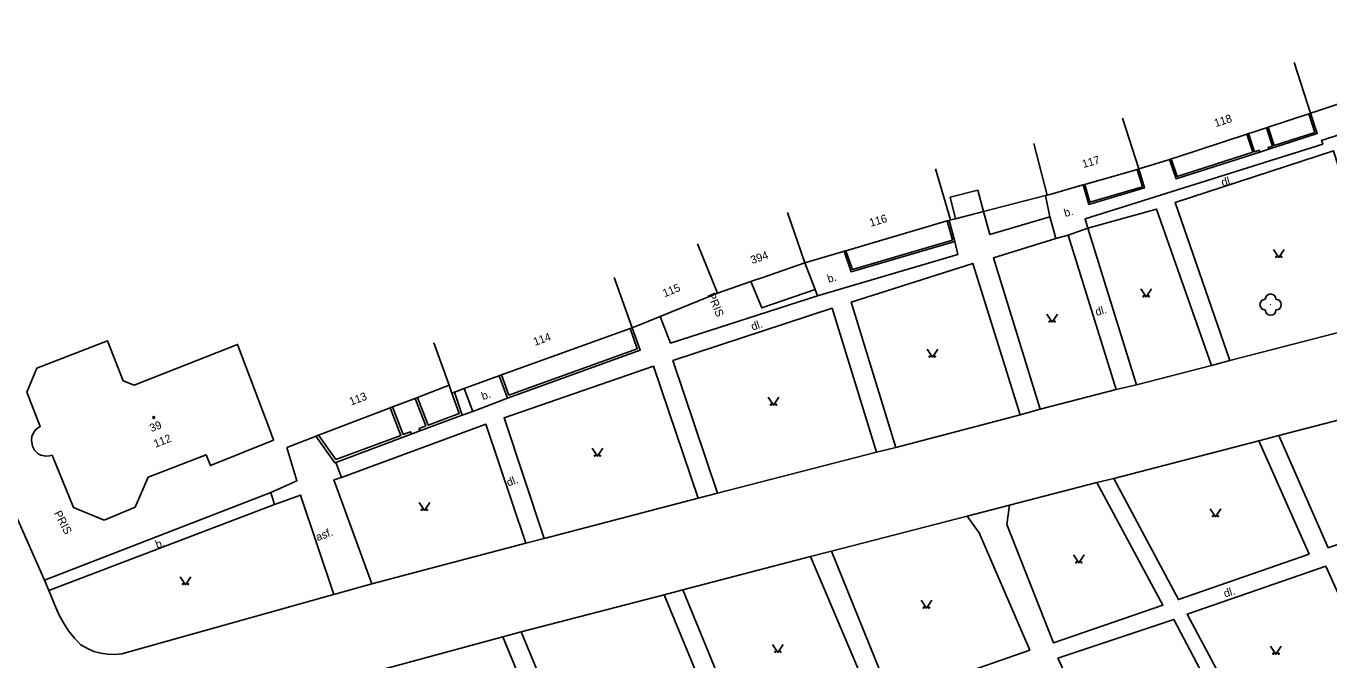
# Model space of a CAD drawing. Extents: x -577457 to -568404, y -1208466 to -1201387.
# Drawn here: x -575095.5 to -574973.4, y -1204045.2 to -1203985.8 of the extents above; entities that cross this region are included whole.
import ezdxf

# ---------------------------------------------------------------- set-up
doc = ezdxf.new("R2010")
doc.units = 0
for name, color, linetype in [('BUDOVY_MĚŘ', 7, 'Continuous'), ('BUDOVY_NEMĚŘ', 7, 'Continuous'), ('POMOC_POPIS', 7, 'Continuous'), ('ROZHRANÍ_PLOCH', 7, 'Continuous'), ('ZELEŇ', 7, 'Continuous'), ('ZN_BUDOV', 7, 'Continuous'), ('ZN_DOPLŇKOVÉ', 7, 'Continuous'), ('ZN_KULTUR', 7, 'Continuous'), ('Č_POPIS_ORIENT', 7, 'Continuous')]:
    doc.layers.add(name, color=color, linetype=linetype)

msp = doc.modelspace()

# ---------------------------------------------------------------- linework, layer by layer
at = {"layer": 'BUDOVY_MĚŘ'}
for points in [[(-574976.64, -1203989.22), (-574975.1, -1203993.98)], [(-574975.26, -1203994.03), (-574979.06, -1203995.28)], [(-574975.1, -1203993.98), (-574975.26, -1203994.03)], [(-574975.1, -1203993.98), (-574974.59, -1203993.81)], [(-574992.74, -1203994.44), (-574991.2, -1203999.2)], [(-574979.22, -1203995.33), (-574979.45, -1203995.41)], [(-574979.06, -1203995.28), (-574979.22, -1203995.33)], [(-574981.07, -1203995.94), (-574987.62, -1203998.09), (-574988.16, -1203998.26)], [(-574980.91, -1203995.89), (-574981.07, -1203995.94)], [(-574980.49, -1203995.75), (-574980.91, -1203995.89)], [(-575001.04, -1203996.81), (-574999.8, -1204001.66)], [(-574988.32, -1203998.31), (-574989.02, -1203998.53)], [(-574988.16, -1203998.26), (-574988.32, -1203998.31)], [(-575010.25, -1203999.18), (-575008.84, -1204003.98)], [(-574991.35, -1203999.24), (-574996.25, -1204000.64)], [(-574991.2, -1203999.2), (-574991.35, -1203999.24)], [(-574990.99, -1203999.13), (-574991.2, -1203999.2)], [(-574996.41, -1204000.69), (-574996.75, -1204000.79)], [(-574996.25, -1204000.64), (-574996.41, -1204000.69)], [(-575005.77, -1204003.19), (-574999.94, -1204001.7)], [(-574999.94, -1204001.7), (-574999.8, -1204001.66)], [(-574999.41, -1204001.55), (-574999.8, -1204001.66)], [(-575024.13, -1204003.27), (-575022.49, -1204007.99)], [(-575008.84, -1204003.98), (-575008.37, -1204003.86)], [(-575008.37, -1204003.86), (-575005.77, -1204003.19)], [(-575018.65, -1204006.86), (-575009.15, -1204004.07)], [(-575009.15, -1204004.07), (-575008.98, -1204004.02)], [(-575008.98, -1204004.02), (-575008.84, -1204003.98)], [(-575032.58, -1204006.2), (-575030.7, -1204010.83)], [(-575019.11, -1204007), (-575018.82, -1204006.91)], [(-575018.82, -1204006.91), (-575018.65, -1204006.86)], [(-575026.53, -1204009.39), (-575022.49, -1204007.99)], [(-575022.49, -1204007.99), (-575021.65, -1204007.74)], [(-575040.38, -1204009.38), (-575038.68, -1204014.08)], [(-575030.7, -1204010.83), (-575027.57, -1204009.75)], [(-575027.57, -1204009.75), (-575027.4, -1204009.69)], [(-575036.06, -1204013.01), (-575030.7, -1204010.83)], [(-575050.94, -1204018.5), (-575038.89, -1204014.16)], [(-575038.89, -1204014.16), (-575038.68, -1204014.08)], [(-575038.68, -1204014.08), (-575038.37, -1204013.95)], [(-575057.29, -1204015.48), (-575055.85, -1204019.47)], [(-575051.43, -1204018.68), (-575051.15, -1204018.58)], [(-575051.15, -1204018.58), (-575050.94, -1204018.5)], [(-575055.85, -1204019.47), (-575058.81, -1204020.6)], [(-575055.85, -1204019.47), (-575055.59, -1204020.19)], [(-575055.35, -1204020.1), (-575054.45, -1204019.77)], [(-575054.45, -1204019.77), (-575054.28, -1204019.71)], [(-575059.04, -1204020.69), (-575059.46, -1204020.85)], [(-575058.81, -1204020.6), (-575059.04, -1204020.69)], [(-575055.59, -1204020.19), (-575055.35, -1204020.1)], [(-575061.37, -1204021.58), (-575068.09, -1204024.15)], [(-575061.14, -1204021.49), (-575061.37, -1204021.58)], [(-575060.72, -1204021.33), (-575061.14, -1204021.49)], [(-575068.33, -1204024.24), (-575068.47, -1204024.29)], [(-575068.09, -1204024.15), (-575068.33, -1204024.24)]]:
    msp.add_lwpolyline(points, dxfattribs=at)
at = {"layer": 'BUDOVY_NEMĚŘ'}
msp.add_lwpolyline([(-575088.18, -1204032.09), (-575091.07, -1204030.91), (-575093.07, -1204026.03), (-575093.32, -1204026.08), (-575093.65, -1204026.12), (-575094.11, -1204026.02), (-575094.38, -1204025.88), (-575094.72, -1204025.55), (-575094.89, -1204025.18), (-575095, -1204024.63), (-575094.97, -1204024.23), (-575094.72, -1204023.76), (-575094.52, -1204023.55), (-575094.17, -1204023.34), (-575095.44, -1204020.11), (-575094.49, -1204017.85), (-575087.87, -1204015.3), (-575086.39, -1204019.05), (-575085.36, -1204019.46), (-575075.68, -1204015.64), (-575072.57, -1204023.89), (-575072.31, -1204024.6), (-575078.22, -1204026.99), (-575078.63, -1204025.97), (-575084.06, -1204028.08), (-575085.29, -1204030.9), (-575088.18, -1204032.09)], dxfattribs=at)
at = {"layer": 'ROZHRANÍ_PLOCH'}
for points in [[(-574995.99, -1204004.75), (-574996.24, -1204003.87), (-574973.96, -1203996.86), (-574974.07, -1203996.52), (-574957.69, -1203991.15), (-574957.42, -1203991.67), (-574939.91, -1203985.81), (-574939.38, -1203987.25)], [(-574982.66, -1204017.14), (-574987.79, -1204002.33), (-574972.94, -1203997.49), (-574968, -1204013.37)], [(-574979.86, -1203997.62), (-574979.01, -1203997.34)], [(-575093.77, -1204037.74), (-575110.49, -1204000)], [(-574999.53, -1204003.67), (-574999.94, -1204001.7)], [(-575005.77, -1204003.19), (-575005.17, -1204005.33), (-574999.53, -1204003.67)], [(-574999.53, -1204003.67), (-574999.24, -1204004.77), (-574998.98, -1204005.71)], [(-574995.99, -1204004.75), (-574989.54, -1204002.96), (-574984.37, -1204017.6)], [(-574997.81, -1204005.41), (-574995.99, -1204004.75)], [(-574995.99, -1204004.75), (-574991.42, -1204019.41)], [(-575021.33, -1204011.08), (-575008.17, -1204007.2), (-575008.43, -1204005.99)], [(-575000.43, -1204021.72), (-575004.83, -1204007.53), (-574998.98, -1204005.71)], [(-574997.81, -1204005.41), (-574998.98, -1204005.71)], [(-574993.32, -1204019.86), (-574997.81, -1204005.41)], [(-575013.96, -1204025.29), (-575018.16, -1204011.69), (-575006.76, -1204008.05), (-575002.32, -1204022.24)], [(-575036.06, -1204013.01), (-575035.09, -1204015.51), (-575021.33, -1204011.08)], [(-575021.33, -1204011.08), (-575021.54, -1204010.5)], [(-575030.69, -1204029.59), (-575034.87, -1204017.15), (-575019.95, -1204012.25), (-575015.8, -1204025.74)], [(-574982.66, -1204017.14), (-574968, -1204013.37)], [(-574984.37, -1204017.6), (-574982.66, -1204017.14)], [(-575046.95, -1204033.82), (-575050.7, -1204022.51), (-575036.68, -1204017.68), (-575032.51, -1204030.05)], [(-574991.42, -1204019.41), (-574984.37, -1204017.6)], [(-575054.45, -1204019.77), (-575053.64, -1204021.91)], [(-574993.32, -1204019.86), (-574991.42, -1204019.41)], [(-575053.64, -1204021.91), (-575050.37, -1204020.66)], [(-575000.43, -1204021.72), (-574993.32, -1204019.86)], [(-575053.64, -1204021.91), (-575054.61, -1204022.27)], [(-575013.96, -1204025.29), (-575003.25, -1204022.5), (-575002.32, -1204022.24)], [(-575002.32, -1204022.24), (-575000.43, -1204021.72)], [(-574978.06, -1204024.16), (-574967.94, -1204021.55)], [(-574978.06, -1204024.16), (-574973.46, -1204034.69), (-574964.49, -1204031.47), (-574964.14, -1204030.9), (-574967.94, -1204021.55)], [(-575048.66, -1204034.25), (-575052.4, -1204023.11), (-575065.94, -1204028.11)], [(-574993.54, -1204028.2), (-574987.48, -1204039.54), (-574975.24, -1204035.29), (-574979.94, -1204024.67)], [(-574993.54, -1204028.2), (-574979.94, -1204024.67)], [(-574979.94, -1204024.67), (-574978.06, -1204024.16)], [(-575070.53, -1204028.6), (-575070.11, -1204028.41), (-575071.07, -1204025.29)], [(-575030.69, -1204029.59), (-575015.8, -1204025.74)], [(-575015.8, -1204025.74), (-575013.96, -1204025.29)], [(-575066.47, -1204026.7), (-575065.94, -1204028.11)], [(-575065.94, -1204028.11), (-575066.65, -1204028.34), (-575063.1, -1204038.08)], [(-574995.13, -1204028.58), (-574993.54, -1204028.2)], [(-575072.55, -1204029.5), (-575093.77, -1204037.74)], [(-575072.55, -1204029.5), (-575070.53, -1204028.6)], [(-575072.23, -1204030.63), (-575072.55, -1204029.5)], [(-575032.51, -1204030.05), (-575030.69, -1204029.59)], [(-575003.33, -1204030.7), (-575003.56, -1204032.5), (-574999.18, -1204043.61), (-574988.94, -1204040.06), (-574995.13, -1204028.58)], [(-575003.33, -1204030.7), (-574995.13, -1204028.58)], [(-575093.37, -1204038.7), (-575072.23, -1204030.63)], [(-575070.12, -1204029.88), (-575072.23, -1204030.63)], [(-575066.66, -1204039.06), (-575069.78, -1204029.76), (-575070.12, -1204029.88)], [(-575046.95, -1204033.82), (-575032.51, -1204030.05)], [(-575007.29, -1204031.73), (-575003.33, -1204030.7)], [(-575020.01, -1204035.01), (-575007.29, -1204031.73)], [(-575020.01, -1204035.01), (-575014.4, -1204048.81), (-575001.42, -1204044.29), (-575006.15, -1204033.29), (-575007.29, -1204031.73)], [(-575048.66, -1204034.25), (-575063.1, -1204038.08)], [(-575046.95, -1204033.82), (-575048.66, -1204034.25)], [(-575033.94, -1204038.63), (-575021.96, -1204035.5)], [(-575033.94, -1204038.63), (-575027.84, -1204053.48), (-575015.96, -1204049.67), (-575021.96, -1204035.5)], [(-575021.96, -1204035.5), (-575020.01, -1204035.01)], [(-574912.63, -1204177.88), (-574922.36, -1204159.6), (-574934.08, -1204138.15), (-574950.93, -1204107.14), (-574981.16, -1204051.23), (-574986.68, -1204040.91), (-574973.68, -1204036.43), (-574971.26, -1204041.76)], [(-575093.77, -1204037.74), (-575093.37, -1204038.7)], [(-575063.1, -1204038.08), (-575066.66, -1204039.06)], [(-575067.11, -1204039.18), (-575086.54, -1204044.63), (-575087.2, -1204044.69), (-575087.86, -1204044.67), (-575088.51, -1204044.57), (-575089.15, -1204044.4), (-575089.76, -1204044.14), (-575090.36, -1204043.8), (-575090.97, -1204043.16), (-575091.53, -1204042.46), (-575092.01, -1204041.71), (-575092.43, -1204040.93), (-575092.71, -1204040.29), (-575093.37, -1204038.7)], [(-575066.66, -1204039.06), (-575067.11, -1204039.18)], [(-575035.69, -1204039.1), (-575049.09, -1204042.57)], [(-575035.69, -1204039.1), (-575029.5, -1204054.06), (-575042.46, -1204058.57), (-575049.09, -1204042.57)], [(-575033.94, -1204038.63), (-575035.69, -1204039.1)], [(-574996.39, -1204050.09), (-574998.78, -1204045.04), (-574987.93, -1204041.41), (-574982.39, -1204051.92), (-574952.04, -1204107.85), (-574935.21, -1204138.91), (-574926.87, -1204154.13), (-574927.75, -1204154.64)], [(-575049.09, -1204042.57), (-575050.81, -1204043.04)], [(-575050.81, -1204043.04), (-575044.18, -1204059.11), (-575067.1, -1204067.02), (-575073.76, -1204049.24)], [(-575050.81, -1204043.04), (-575073.76, -1204049.24)]]:
    msp.add_lwpolyline(points, dxfattribs=at)
at = {"layer": 'ZELEŇ'}
msp.add_circle((-574978.84, -1204011.91), 0.0005, dxfattribs=at)
for centre, start, end in [((-574978.84, -1204011.41), 0, 180), ((-574979.34, -1204011.91), 90, 270), ((-574978.84, -1204012.41), 180, 360), ((-574978.34, -1204011.91), 270, 90)]:
    msp.add_arc(centre, 0.5, start, end, dxfattribs=at)
at = {"layer": 'ZN_BUDOV'}
msp.add_circle((-575083.54, -1204022.48), 0.0875, dxfattribs=at)
at = {"layer": 'ZN_DOPLŇKOVÉ'}
for points in [[(-574974.59, -1203993.81), (-574971.8, -1203992.89)], [(-574975.26, -1203994.03), (-574974.69, -1203995.78), (-574978.52, -1203997.01), (-574979.06, -1203995.28)], [(-574975.1, -1203993.98), (-574974.47, -1203995.89), (-574979.01, -1203997.34)], [(-574979.01, -1203997.34), (-574979.06, -1203997.18), (-574978.68, -1203997.06), (-574979.22, -1203995.33)], [(-574981.07, -1203995.94), (-574980.51, -1203997.64), (-574987.59, -1203999.9), (-574988.16, -1203998.26)], [(-574980.91, -1203995.89), (-574980.35, -1203997.59), (-574979.92, -1203997.45), (-574979.86, -1203997.62)], [(-574979.45, -1203995.41), (-574980.49, -1203995.75)], [(-574979.86, -1203997.62), (-574987.7, -1204000.11), (-574988.32, -1203998.31)], [(-574989.02, -1203998.53), (-574990.99, -1203999.13)], [(-574991.2, -1203999.2), (-574990.66, -1204000.97), (-574995.89, -1204002.52), (-574996.41, -1204000.69)], [(-574991.35, -1203999.24), (-574990.86, -1204000.87), (-574995.78, -1204002.32), (-574996.25, -1204000.64)], [(-575008.37, -1204003.86), (-575008.89, -1204001.85), (-575006.29, -1204001.19), (-575005.77, -1204003.19)], [(-574996.75, -1204000.79), (-574999.41, -1204001.55)], [(-575009.15, -1204004.07), (-575008.65, -1204005.87), (-575018.05, -1204008.61), (-575018.65, -1204006.86)], [(-575008.98, -1204004.02), (-575008.43, -1204005.99)], [(-575008.43, -1204005.99), (-575018.17, -1204008.83), (-575018.82, -1204006.91)], [(-575021.65, -1204007.74), (-575019.11, -1204007)], [(-575022.49, -1204007.99), (-575021.54, -1204010.5)], [(-575021.54, -1204010.5), (-575026.55, -1204012.2), (-575027.57, -1204009.75)], [(-575027.4, -1204009.69), (-575026.53, -1204009.39)], [(-575038.37, -1204013.95), (-575036.06, -1204013.01)], [(-575038.89, -1204014.16), (-575038.21, -1204016.04), (-575050.24, -1204020.38), (-575050.94, -1204018.5)], [(-575038.68, -1204014.08), (-575037.93, -1204016.18), (-575050.37, -1204020.66)], [(-575050.37, -1204020.66), (-575051.15, -1204018.58)], [(-575054.28, -1204019.71), (-575051.43, -1204018.68)], [(-575059.46, -1204020.85), (-575060.72, -1204021.33)], [(-575059.04, -1204020.69), (-575058.04, -1204023.28), (-575058.66, -1204023.51), (-575058.58, -1204023.74)], [(-575055.59, -1204020.19), (-575054.92, -1204022.12), (-575057.81, -1204023.19), (-575058.81, -1204020.6)], [(-575055.35, -1204020.1), (-575054.61, -1204022.27)], [(-575061.37, -1204021.58), (-575060.37, -1204024.16), (-575066.46, -1204026.43), (-575068.09, -1204024.15)], [(-575061.14, -1204021.49), (-575060.14, -1204024.07), (-575059.47, -1204023.82), (-575059.39, -1204024.06)], [(-575054.61, -1204022.27), (-575058.58, -1204023.74)], [(-575068.47, -1204024.29), (-575071.07, -1204025.29)], [(-575066.47, -1204026.7), (-575066.55, -1204026.73), (-575068.33, -1204024.24)], [(-575059.39, -1204024.06), (-575066.47, -1204026.7)], [(-575058.58, -1204023.74), (-575059.39, -1204024.06)]]:
    msp.add_lwpolyline(points, dxfattribs=at)
at = {"layer": 'ZN_KULTUR'}
for points in [[(-574978.58, -1204006.74), (-574978.08, -1204007.49), (-574977.58, -1204006.74)], [(-574991.01, -1204010.43), (-574990.51, -1204011.18), (-574990.01, -1204010.43)], [(-574999.83, -1204012.8), (-574999.33, -1204013.55), (-574998.83, -1204012.8)], [(-575011.05, -1204016.08), (-575010.55, -1204016.83), (-575010.05, -1204016.08)], [(-575025.93, -1204020.58), (-575025.43, -1204021.33), (-575024.93, -1204020.58)], [(-575042.45, -1204025.37), (-575041.95, -1204026.12), (-575041.45, -1204025.37)], [(-575058.67, -1204030.44), (-575058.17, -1204031.19), (-575057.67, -1204030.44)], [(-574984.52, -1204031.04), (-574984.02, -1204031.79), (-574983.52, -1204031.04)], [(-574997.32, -1204035.36), (-574996.82, -1204036.11), (-574996.32, -1204035.36)], [(-575081.05, -1204037.4), (-575080.55, -1204038.15), (-575080.05, -1204037.4)], [(-575011.61, -1204039.6), (-575011.11, -1204040.35), (-575010.61, -1204039.6)], [(-575025.53, -1204043.74), (-575025.03, -1204044.49), (-575024.53, -1204043.74)], [(-574978.84, -1204043.91), (-574978.34, -1204044.66), (-574977.84, -1204043.91)]]:
    msp.add_lwpolyline(points, dxfattribs=at)
for centre in [(-574978.33, -1204007.44), (-574977.83, -1204007.44), (-574990.76, -1204011.13), (-574990.26, -1204011.13), (-574999.58, -1204013.5), (-574999.08, -1204013.5), (-575010.8, -1204016.78), (-575010.3, -1204016.78), (-575025.68, -1204021.28), (-575025.18, -1204021.28), (-575042.2, -1204026.07), (-575041.7, -1204026.07), (-575058.42, -1204031.14), (-575057.92, -1204031.14), (-574984.27, -1204031.74), (-574983.77, -1204031.74), (-574997.07, -1204036.06), (-574996.57, -1204036.06), (-575080.8, -1204038.1), (-575080.3, -1204038.1), (-575011.36, -1204040.3), (-575010.86, -1204040.3), (-575025.28, -1204044.44), (-575024.78, -1204044.44), (-574978.59, -1204044.61), (-574978.09, -1204044.61)]:
    msp.add_circle(centre, 0.05, dxfattribs=at)

# ---------------------------------------------------------------- texts
at = {"layer": 'POMOC_POPIS'}
for s, rotation, p in [('dl.', 15.96, (-574983.34, -1204000.84)), ('b.', 15.96, (-574998.09, -1204003.71)), ('b.', 16.38, (-575020.27, -1204009.88)), ('PRIS', 292.88, (-575031.66, -1204010.98)), ('dl.', 15.96, (-574995.16, -1204012.98)), ('dl.', 18.2, (-575027.4, -1204014.35)), ('b.', 19.85, (-575052.66, -1204020.87)), ('dl.', 20.88, (-575050.29, -1204028.97)), ('PRIS', 297.41, (-575092.91, -1204031.44)), ('asf.', 20.9, (-575068.18, -1204034.08)), ('b.', 20.9, (-575083.21, -1204034.78)), ('dl.', 18.44, (-574983.1, -1204039.37))]:
    msp.add_text(s, height=0.75, rotation=rotation, dxfattribs=at).set_placement(p)
at = {"layer": 'Č_POPIS_ORIENT'}
for s, rotation, p in [('118', 17.95, (-574983.99, -1203995.28)), ('117', 15.96, (-574996.39, -1203999.12)), ('116', 16.38, (-575016.33, -1204004.62)), ('394', 19.11, (-575027.44, -1204008.12)), ('115', 22.14, (-575035.65, -1204011.23)), ('114', 19.85, (-575047.8, -1204015.78)), ('113', 20.9, (-575065.04, -1204021.38)), ('39', 21.65, (-575083.75, -1204023.87)), ('112', 21.65, (-575083.37, -1204025.33))]:
    msp.add_text(s, height=0.75, rotation=rotation, dxfattribs=at).set_placement(p)

doc.saveas('drawing.dxf')
